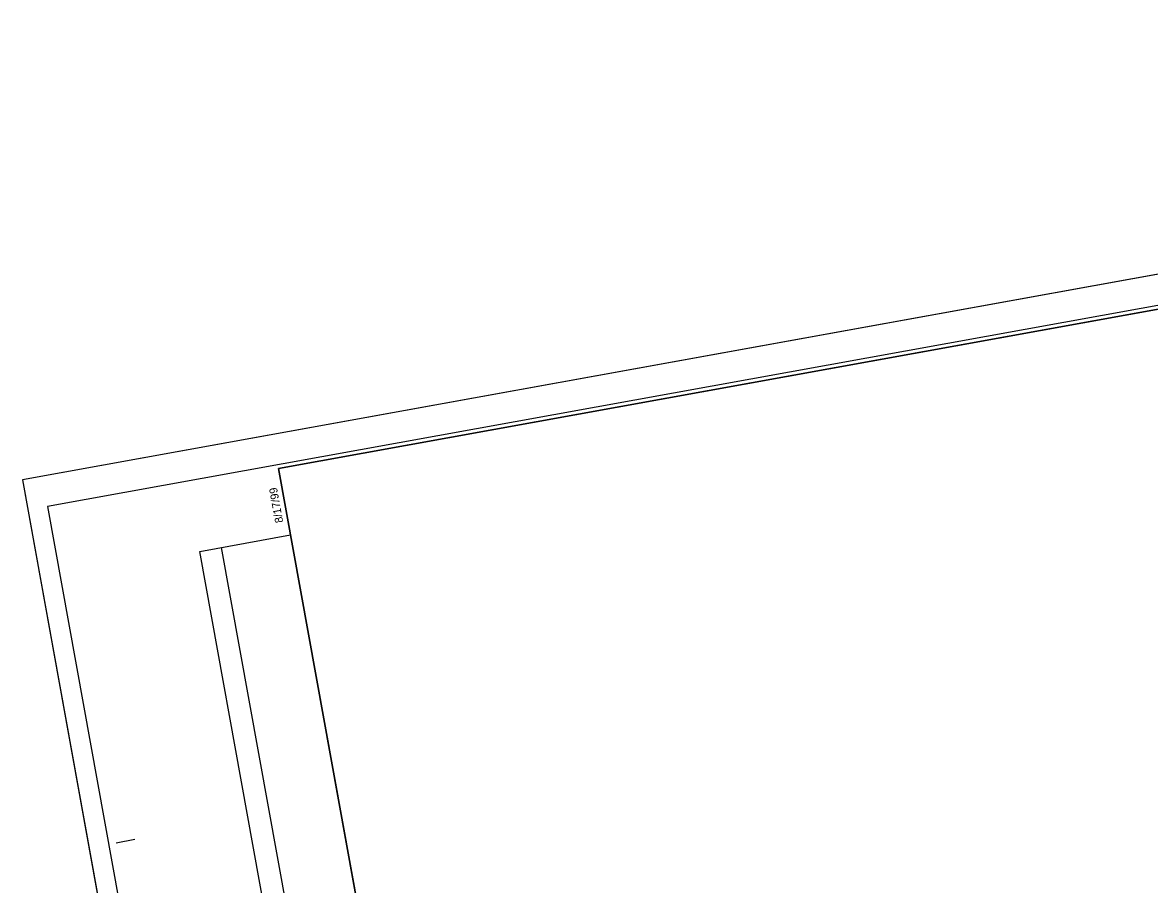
# Model space of a CAD drawing. Extents: x 1617779 to 1622406, y 896496 to 899510.
# Drawn here: x 1620151 to 1620890, y 898480 to 899045 of the extents above; entities that cross this region are included whole.
import ezdxf

# ---------------------------------------------------------------- set-up
doc = ezdxf.new("R2010")
doc.units = 0
for name, color, linetype in [('ControlPoints', 7, 'Continuous'), ('Exist Vertical Profile Ground Line', 7, 'Continuous'), ('Exist Vertical Profile Horizontal Axis Label Major', 7, 'Continuous'), ('Observations', 7, 'Continuous'), ('Prop Horizontal Alignment', 7, 'Continuous'), ('Setups', 7, 'Continuous')]:
    doc.layers.add(name, color=color, linetype=linetype)

msp = doc.modelspace()

# ---------------------------------------------------------------- linework, layer by layer
at = {"layer": 'ControlPoints'}
msp.add_lwpolyline([(1620345.76, 897667.32), (1622002.34, 897967.18), (1621807.3, 899044.67), (1620150.72, 898744.81)], close=True, dxfattribs=at)
at = {"layer": 'Exist Vertical Profile Ground Line'}
msp.add_line((1620422.04, 897922.5), (1620281.2, 898700.5), dxfattribs=at)
msp.add_lwpolyline([(1620407.72, 897919.89), (1620266.9, 898697.89), (1620326.46, 898708.7), (1620467.29, 897930.69)], close=True, dxfattribs=at)
at = {"layer": 'Exist Vertical Profile Horizontal Axis Label Major'}
for p, q in [((1620318.55, 898752.34), (1620318.55, 898752.34)), ((1620212.06, 898506.92), (1620224.37, 898509.18))]:
    msp.add_line(p, q, dxfattribs=at)
for points in [[(1621794.6, 899019.52), (1620318.55, 898752.34), (1620505.57, 897719.13), (1621981.6, 897986.3)], [(1620505.57, 897719.13), (1620318.53, 898752.31), (1621597.72, 898983.9), (1621624.47, 898836.23), (1621821.31, 898871.85), (1621981.6, 897986.3)]]:
    msp.add_lwpolyline(points, close=True, dxfattribs=at)
at = {"layer": 'Observations'}
msp.add_lwpolyline([(1620318.53, 898752.31), (1620505.57, 897719.13), (1621981.59, 897986.3), (1621832.23, 898811.41), (1621596.81, 898768.79), (1621559.14, 898976.9)], close=True, dxfattribs=at)
at = {"layer": 'Prop Horizontal Alignment'}
for p, q in [((1621807.3, 899044.67), (1620150.72, 898744.81)), ((1620150.72, 898744.81), (1620345.76, 897667.32))]:
    msp.add_line(p, q, dxfattribs=at)
at = {"layer": 'Setups'}
msp.add_lwpolyline([(1620354.99, 897689.32), (1621994.33, 897986.07), (1621806.44, 899024.19), (1620167.07, 898727.45)], close=True, dxfattribs=at)

# ---------------------------------------------------------------- texts
at = {"layer": 'Exist Vertical Profile Horizontal Axis Label Major'}
msp.add_text('8/17/99', height=5.25, rotation=100.25995, dxfattribs=at).set_placement((1620321.65, 898717.1))

doc.saveas('drawing.dxf')
